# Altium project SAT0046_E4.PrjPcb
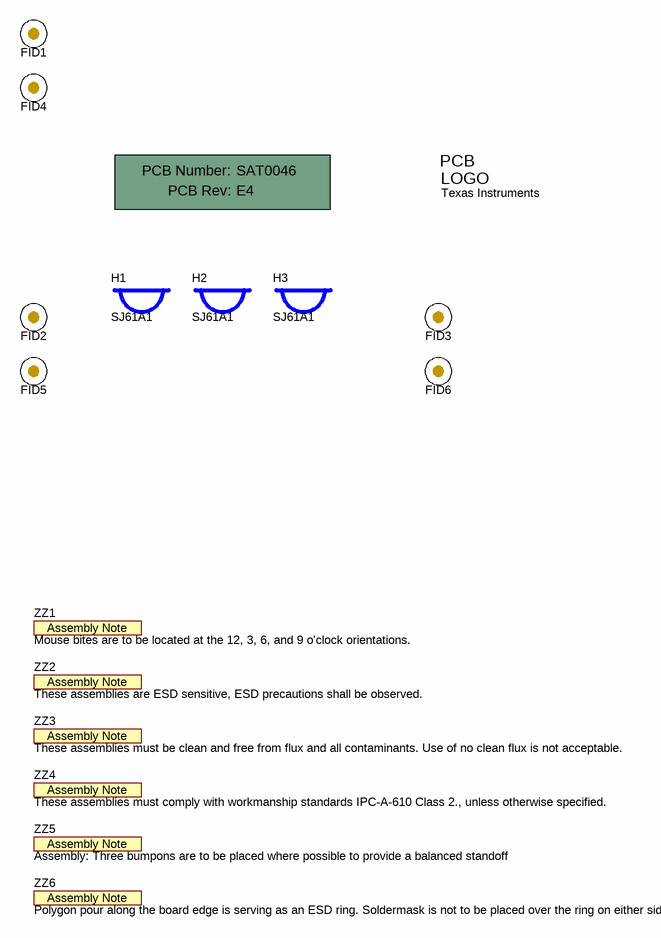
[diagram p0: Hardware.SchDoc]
TechSupport: http://www.ti.com/support; SCH_Rev: E4; PRJ_Title: SAT0046; PRJ_Number: SAT0046; PRJ_Engineer: Ajinder Singh; PRJ_Customer: Public Release; PCB_Rev: E4; PCB_Layout: Krypton Solutions LLC; CopyrightYear: 2012
3 sheets, 111 parts. Net scope: global (net labels, ports and power ports of the same name join across sheets).
Board file: SAT0046_E4.PcbDoc
Sheets:
  Hardware.SchDoc
  SAT0046_E4_Temp_Transmitter_System.SchDoc
  SAT0046_E4_MSP430.SchDoc

## Sheet Hardware.SchDoc: Hardware
size 431 x 279 mm; Date: Not shown in title block; ApprovedBy: Not shown in title block; CheckedBy: Not shown in title block; Author: Not shown in title block; CompanyName: Not shown in title block; DrawnBy: Ajinder Singh; Engineer: Not shown in title block; Organization: Not shown in title block; Address1: Not shown in title block; Address2: Not shown in title block; Address3: Not shown in title block; Address4: Not shown in title block; DocumentNumber: 1; Revision: Use project parameter SCH_Rev; SheetNumber: 1; SheetTotal: 1; PageSetup: Record=PageOptions|CenterHorizontal=True|CenterVertical=True|PrintScale=1.00|XCorrection=1.00|YCorrection=1.00|PrintKind=0|BorderSize=5000000|LeftOffset=0|BottomOffset=0|Orientation=2|PaperLength=1000|PaperWidth=1000|Scale=100|PaperSource=15|PrintQuality=600|MediaType=1|DitherType=10|PaperKind=Letter|PrintScaleMode=1

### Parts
!PCB1  Printed Circuit Board  (value not drawn)  (mechanical)
FID1  Fiducial  [Fiducial10-20]  (value not drawn)
FID2  Fiducial  [Fiducial10-20]  (value not drawn)
FID3  Fiducial  [Fiducial10-20]  (value not drawn)
FID4  Fiducial  [Fiducial10-20]  (value not drawn)
FID5  Fiducial  [Fiducial10-20]  (value not drawn)
FID6  Fiducial  [Fiducial10-20]  (value not drawn)
H1  SJ61A1  [Bumpon_SJ61A1]
H2  SJ61A1  [Bumpon_SJ61A1]
H3  SJ61A1  [Bumpon_SJ61A1]
Logo1  Texas Instruments  [TI_Symbol_Overlay_Small]  (no BOM)
ZZ1  Mouse bites are to be located at the 12, 3, 6, and 9 o'clock orientations.  [AssemblyNote]  (no BOM)
ZZ2  These assemblies are ESD sensitive, ESD precautions shall be observed.  [AssemblyNote]  (no BOM)
ZZ3  These assemblies must be clean and free from flux and all contaminants. Use of no clean flux is not acceptable.  [AssemblyNote]  (no BOM)
ZZ4  These assemblies must comply with workmanship standards IPC-A-610 Class 2., unless otherwise specified.  [AssemblyNote]  (no BOM)
ZZ5  Assembly: Three bumpons are to be placed where possible to provide a balanced standoff  [AssemblyNote]  (no BOM)
ZZ6  Polygon pour along the board edge is serving as an ESD ring. Soldermask is not to be placed over the ring on either side.  [AssemblyNote]  (no BOM)

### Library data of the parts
!PCB1 = PCB: Manufacturer: Any; PartNumber: SAT0046; SymbolCreator: a0412235
FID1-FID6 = Fiducial: Fiducial mark.  There is nothing to buy or mount.; SymbolCreator: codlsc
H1-H3 = SJ61A1: Bumpon, Cylindrical, 0.312 X 0.200, Black; Manufacturer: 3M; SymbolCreator: a0412235
Logo1 = TI_Logo: Texas Instrument Corporate Signature; SymbolCreator: codlsc
ZZ1-ZZ6 = AssemblyNote: SymbolCreator: codlsc

## Sheet SAT0046_E4_Temp_Transmitter_System.SchDoc: Temp_Transmitter_System
size 431 x 279 mm; Date: Not shown in title block; ApprovedBy: Not shown in title block; CheckedBy: Not shown in title block; Author: Not shown in title block; CompanyName: Not shown in title block; DrawnBy: Ajinder Singh; Engineer: Ajinder Singh; Organization: Not shown in title block; Address1: Not shown in title block; Address2: Not shown in title block; Address3: Not shown in title block; Address4: Not shown in title block; DocumentNumber: 1; Revision: E2; SheetNumber: 1; SheetTotal: 1; PageSetup: Record=PageOptions|CenterHorizontal=True|CenterVertical=True|PrintScale=1.00|XCorrection=1.00|YCorrection=1.00|PrintKind=0|BorderSize=5000000|LeftOffset=0|BottomOffset=0|Orientation=2|PaperLength=1000|PaperWidth=1000|Scale=100|PaperSource=15|PrintQuality=600|MediaType=1|DitherType=10|PaperKind=Letter|PrintScaleMode=1
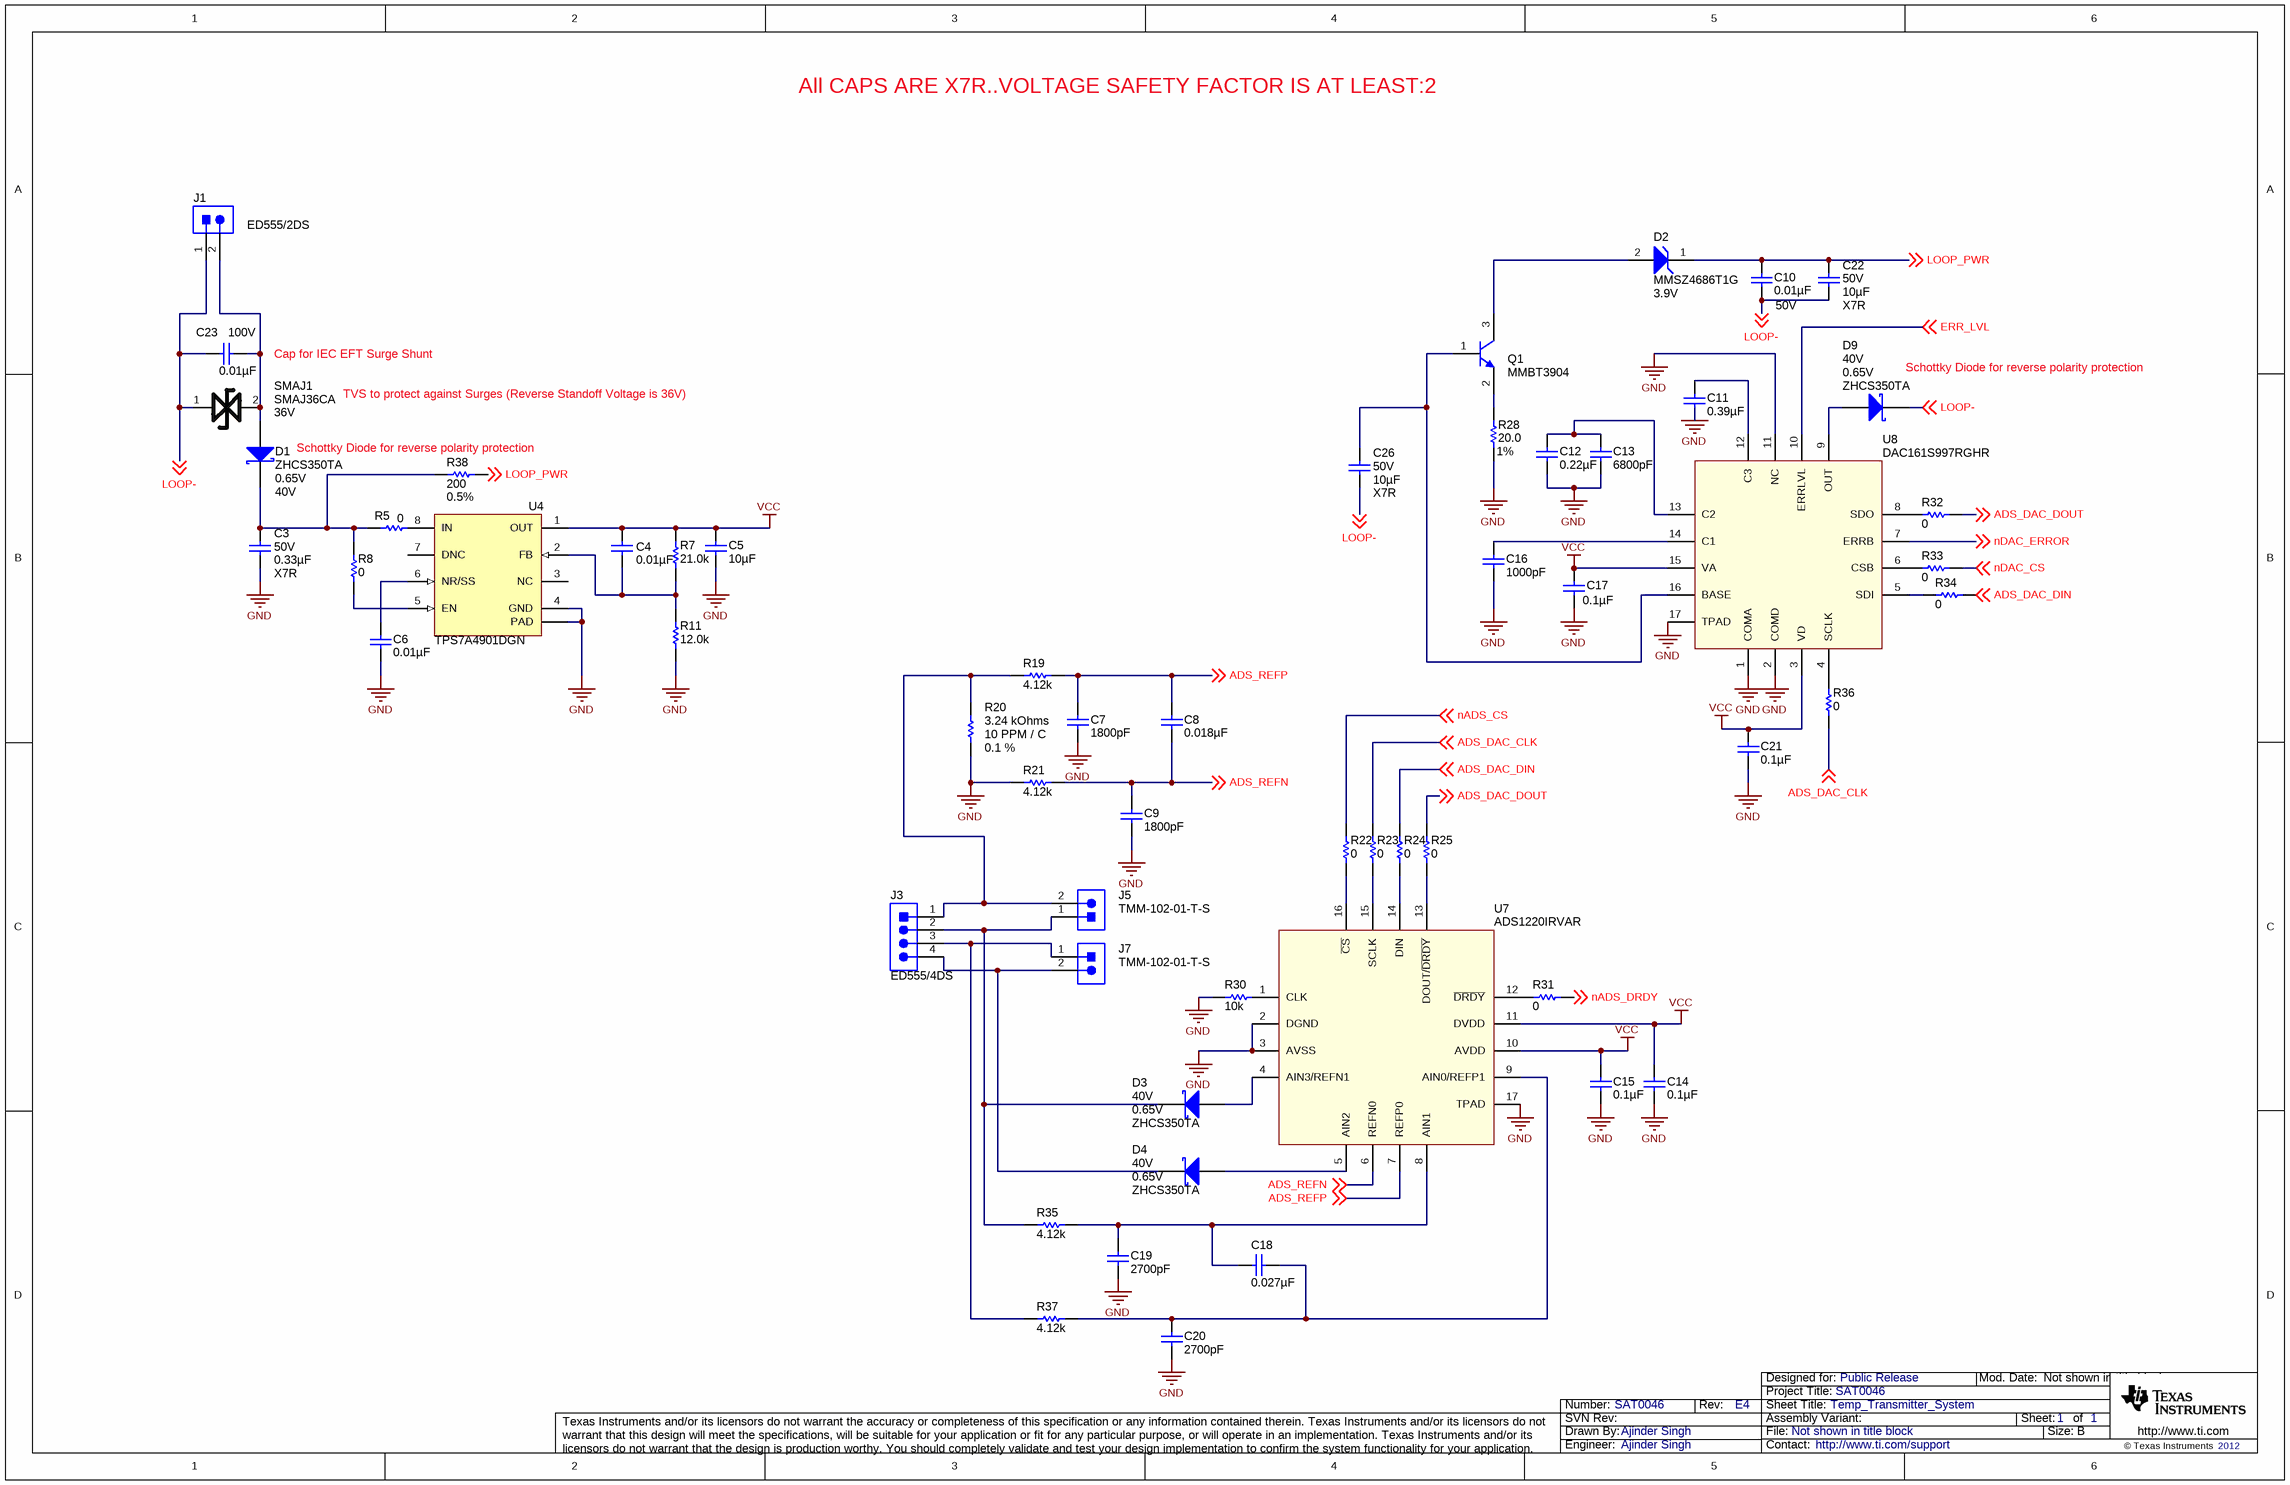
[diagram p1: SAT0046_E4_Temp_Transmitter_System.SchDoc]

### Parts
C3  ValueDisplayed: 0.33µF  Value2: 50V  TempCo: X7R  [1206]  (hidden comment: 12065C334KAT2A)
C4  ValueDisplayed: 0.01µF  [0603]  (hidden comment: C0603C103J5RACTU)
C5  ValueDisplayed: 10µF  [1206]  (hidden comment: GRM31CR71C106KAC7L)
C6  ValueDisplayed: 0.01µF  [0603]  (hidden comment: C0603C103J5RACTU)
C7  value 1800pF  [0603]  (hidden comment: Used in BOM report)
C8  ValueDisplayed: 0.018µF  [0603]  (hidden comment: C0603C183K1RACTU)
C9  value 1800pF  [0603]  (hidden comment: Used in BOM report)
C10  ValueDisplayed: 0.01µF  Value2: 50V  [0603]  (hidden comment: C0603C103J5RACTU)
C11  ValueDisplayed: 0.39µF  [1206]  (hidden comment: GRM31MR71H394KA01L)
C12  ValueDisplayed: 0.22µF  [1206]  (hidden comment: C1206C224J5RACTU)
C13  ValueDisplayed: 6800pF  [0603]  (hidden comment: C0603C682J5RACTU)
C14  ValueDisplayed: 0.1µF  [0603]  (hidden comment: C0603X104K4RACTU)
C15  ValueDisplayed: 0.1µF  [0603]  (hidden comment: C0603X104K4RACTU)
C16  ValueDisplayed: 1000pF  [0603]  (hidden comment: C0603C102J5RACTU)
C17  ValueDisplayed: 0.1µF  [0603]  (hidden comment: C0603X104K4RACTU)
C18  ValueDisplayed: 0.027µF  [0603]  (hidden comment: C0603C273K1RACTU)
C19  value 2700pF  [0603]  (hidden comment: Used in BOM report)
C20  value 2700pF  [0603]  (hidden comment: Used in BOM report)
C21  ValueDisplayed: 0.1µF  [0603]  (hidden comment: C0603X104K4RACTU)
C22  ValueDisplayed: 10µF  Value2: 50V  TempCo: X7R  [1210]  (hidden comment: GRM32ER71H106KA12L)
C23  ValueDisplayed: 0.01µF  Value2: 100V  [0603]  (hidden comment: C1608X7R2A103K)
C26  ValueDisplayed: 10µF  Value2: 50V  TempCo: X7R  [1210]  (hidden comment: GRM32ER71H106KA12L)
D1  ZHCS350TA  value 0.65V  Value2: 40V  [SOD-523]
D2  MMSZ4686T1G  value 3.9V  [SOD-123]
D3  ZHCS350TA  value 0.65V  Value2: 40V  [SOD-523]
D4  ZHCS350TA  value 0.65V  Value2: 40V  [SOD-523]
D9  ZHCS350TA  value 0.65V  Value2: 40V  [SOD-523]
J1  ED555/2DS  [TERM_BLK_ED555-2DS]
J3  ED555/4DS  [TERM_BLK_ED555-4DS]
J5  TMM-102-01-T-S  [CONN_TMM-102-01-T-S]
J7  TMM-102-01-T-S  [CONN_TMM-102-01-T-S]
Q1  MMBT3904  [SOT-23]
R5  value 0  [0402]  (hidden comment: CRCW04020000Z0ED)
R7  value 21.0k  [0603]  (hidden comment: RC0603FR-0721KL)
R8  value 0  [0402]  (hidden comment: CRCW04020000Z0ED)
R11  value 12.0k  [0603]  (hidden comment: RC0603FR-0712KL)
R19  value 4.12k  [1206]  (hidden comment: ERA-8AEB4121V)
R20  value 3.24 kOhms  TempCo: 10 PPM / C  Tolerance_%: 0.1 %  [1206]  (hidden comment: PFC-W1206R-12-3241-B)
R21  value 4.12k  [1206]  (hidden comment: ERA-8AEB4121V)
R22  value 0  [0402]  (hidden comment: CRCW04020000Z0ED)
R23  value 0  [0402]  (hidden comment: CRCW04020000Z0ED)
R24  value 0  [0402]  (hidden comment: CRCW04020000Z0ED)
R25  value 0  [0402]  (hidden comment: CRCW04020000Z0ED)
R28  value 20.0  Value1: 1%  [0603]  (hidden comment: CRCW060320R0FKEA)
R30  value 10k  [0402]  (hidden comment: CRCW040210K0FKEDHP)
R31  value 0  [0402]  (hidden comment: CRCW04020000Z0ED)
R32  value 0  [0402]  (hidden comment: CRCW04020000Z0ED)
R33  value 0  [0402]  (hidden comment: CRCW04020000Z0ED)
R34  value 0  [0402]  (hidden comment: CRCW04020000Z0ED)
R35  value 4.12k  [1206]  (hidden comment: ERA-8AEB4121V)
R36  value 0  [0402]  (hidden comment: CRCW04020000Z0ED)
R37  value 4.12k  [1206]  (hidden comment: ERA-8AEB4121V)
R38  value 200  Value1: 0.5%  [0603]  (hidden comment: RT0603DRE07200RL)
SMAJ1  Voltage - Reverse Standoff (Typ): 36V  [SMAJ36CA]  (hidden comment: SMAJ36CA)
U4  TPS7A4901DGN  [DGN0008D_N]
U7  ADS1220IRVAR  [ADS1220IRVAR]
U8  DAC161S997RGHR  [DAC161S997RGHR]

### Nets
GND: C3.2 C5.2 C6.2 C7.2 C9.2 C11.2 C12.2 C13.2 C14.2 C15.2 C16.2 C17.2 C19.2 C20.2 C21.2 R11.1 R20.1 R21.1 R28.1 R30.1 U4.4(GND) U4.9(PAD) U7.2(DGND) U7.3(AVSS) U7.17(TPAD) U8.1(COMA) U8.2(COMD) U8.11(NC) U8.17(TPAD)
VCC: C4.2 C5.1 C14.1 C15.1 C17.1 C21.1 R7.2 U4.1(OUT) U7.10(AVDD) U7.11(DVDD) U8.3(VD) U8.15(VA)
ADS_DAC_CLK: R23.2 R36.2 ; off-sheet ADS_DAC_CLK
ADS_DAC_DIN: R24.2 R34.1 ; off-sheet ADS_DAC_DIN
ADS_DAC_DOUT: R25.2 R32.1 ; off-sheet ADS_DAC_DOUT
ADS_REFN: C8.2 C9.1 R21.2 U7.6(REFN0) ; off-sheet ADS_REFN
ADS_REFP: C7.1 C8.1 R19.2 U7.7(REFP0) ; off-sheet ADS_REFP
ERR_LVL: U8.10(ERRLVL) ; off-sheet ERR_LVL
LOOP-: C10.2 C22.2 C23.2 C26.2 D9.1(K) J1.1 SMAJ1.1 ; off-sheet LOOP-
LOOP_PWR: C10.1 C22.1 D2.1(K) R38.2 ; off-sheet LOOP_PWR
nADS_CS: R22.2 ; off-sheet nADS_CS
nADS_DRDY: R31.1 ; off-sheet nADS_DRDY
nDAC_CS: R33.1 ; off-sheet nDAC_CS
nDAC_ERROR: U8.7(ERRB) ; off-sheet nDAC_ERROR
NetC3_1: C3.1 D1.1(K) R5.2 R8.1 R38.1
NetC4_1: C4.1 R7.1 R11.2 U4.2(FB)
NetC6_1: C6.1 U4.6(NR/SS)
NetC11_1: C11.1 U8.12(C3)
NetC12_1: C12.1 C13.1 U8.13(C2)
NetC16_1: C16.1 U8.14(C1)
NetC18_1: C18.1 C20.1 R37.2 U7.9(AIN0/REFP1)
NetC18_2: C18.2 C19.1 R35.2 U7.8(AIN1)
NetC23_1: C23.1 D1.2(A) J1.2 SMAJ1.2
NetC26_1: C26.1 Q1.1(B) U8.16(BASE)
NetD2_2: D2.2(A) Q1.3(C)
NetD3_1: D3.1(K) J3.2 J5.1 R35.1
NetD3_2: D3.2(A) U7.4(AIN3/REFN1)
NetD4_1: D4.1(K) J3.4 J7.2
NetD4_2: D4.2(A) U7.5(AIN2)
NetD9_2: D9.2(A) U8.9(OUT)
NetJ3_1: J3.1 J5.2 R19.1 R20.2
NetJ3_3: J3.3 J7.1 R37.1
NetQ1_2: Q1.2(E) R28.2
NetR5_1: R5.1 U4.8(IN)
NetR8_2: R8.2 U4.5(EN)
NetR22_1: R22.1 U7.16(~{CS})
NetR23_1: R23.1 U7.15(SCLK)
NetR24_1: R24.1 U7.14(DIN)
NetR25_1: R25.1 U7.13(DOUT/~{DRDY})
NetR30_2: R30.2 U7.1(CLK)
NetR31_2: R31.2 U7.12(~{DRDY})
NetR32_2: R32.2 U8.8(SDO)
NetR33_2: R33.2 U8.6(CSB)
NetR34_2: R34.2 U8.5(SDI)
NetR36_1: R36.1 U8.4(SCLK)

Not connected (* = marked no-connect by the designer): U4 3(NC) 7(DNC)

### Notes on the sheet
- All CAPS ARE X7R..VOLTAGE SAFETY FACTOR IS AT LEAST:2
- Cap for IEC EFT Surge Shunt
- (near D9) Schottky Diode for reverse
- polarity protection
- TVS to protect against Surges (Reverse Standoff Voltage is 36V)
- Schottky Diode for reverse
- (near R38) polarity protection

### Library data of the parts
C3 = 12065C334KAT2A: CAP, CERM, 0.33uF, 50V, +/-10%, X7R, 1206; Manufacturer: AVX; Polarized: N; CompType: Capacitor; U/M: EA; Cap_F: 0.00000033; Tolerance_%: 10; ESR_Ohm: 0.021; Value1: 0.021 ohm; VDC_V: 50; TaMin_C: -55; TaMax_C: 125
C4 C6 C10 = C0603C103J5RACTU: CAP, CERM, 0.01uF, 50V, +/-5%, X7R, 0603; Manufacturer: Kemet; Polarized: N; CompType: Capacitor; U/M: EA; Cap_F: 0.00000001; Tolerance_%: 5; Value1: Unknown; VDC_V: 50; TaMin_C: -55; TaMax_C: 125
C5 = GRM31CR71C106KAC7L: CAP, CERM, 10uF, 16V, +/-10%, X7R, 1206; Manufacturer: MuRata; Polarized: N; CompType: Capacitor; U/M: EA; Cap_F: 0.00001; Tolerance_%: 10; Value1: Unknown; VDC_V: 16; TaMin_C: -55; TaMax_C: 125
C7 C9 = C0603C182K1RACTU: CAP CER 1800PF 100V 10% X7R 0603; SymbolVersion: use current date i.e. 2008-05-20; SymbolCreator: Use a-id; CompType: Used in some BOM reports.  Useful for finding later.; U/M: EA, IN, or GM
C8 = C0603C183K1RACTU: CAP, CERM, 0.018uF, 100V, +/-10%, X7R, 0603; Manufacturer: Kemet; Polarized: N; CompType: Capacitor; U/M: EA; Cap_F: 0.000000018; Tolerance_%: 10; Value1: Unknown; VDC_V: 100; TaMin_C: -55; TaMax_C: 125
C11 = GRM31MR71H394KA01L: CAP, CERM, 0.39uF, 50V, +/-10%, X7R, 1206; Manufacturer: MuRata; Polarized: N; CompType: Capacitor; U/M: EA; Cap_F: 0.00000039; Tolerance_%: 10; Value1: Unknown; VDC_V: 50; TaMin_C: -55; TaMax_C: 125
C12 = C1206C224J5RACTU: CAP, CERM, 0.22uF, 50V, +/-5%, X7R, 1206; Manufacturer: Kemet; Polarized: N; CompType: Capacitor; U/M: EA; Cap_F: 0.00000022; Tolerance_%: 5; ESR_Ohm: 0.081; Value1: 0.081 ohm; VDC_V: 50; IRMS_A: 1.95; TaMin_C: -55; TaMax_C: 125
C13 = C0603C682J5RACTU: CAP, CERM, 6800pF, 50V, +/-5%, X7R, 0603; Manufacturer: Kemet; Polarized: N; CompType: Capacitor; U/M: EA; Cap_F: 0.0000000068; Tolerance_%: 5; Value1: Unknown; VDC_V: 50; TaMin_C: -55; TaMax_C: 125
C14 C15 C17 C21 = C0603X104K4RACTU: CAP, CERM, 0.1uF, 16V, +/-10%, X7R, 0603; Manufacturer: Kemet; Polarized: N; CompType: Capacitor; U/M: EA; Cap_F: 0.0000001; Tolerance_%: 10; Value1: Unknown; VDC_V: 16; TaMin_C: -55; TaMax_C: 125
C16 = C0603C102J5RACTU: CAP, CERM, 1000pF, 50V, +/-5%, X7R, 0603; Manufacturer: Kemet; Polarized: N; CompType: Capacitor; U/M: EA; Cap_F: 0.000000001; Tolerance_%: 5; Value1: Unknown; VDC_V: 50; TaMin_C: -55; TaMax_C: 125
C18 = C0603C273K1RACTU: CAP, CERM, 0.027uF, 100V, +/-10%, X7R, 0603; Manufacturer: Kemet; Polarized: N; CompType: Capacitor; U/M: EA; Cap_F: 0.000000027; Tolerance_%: 10; Value1: Unknown; VDC_V: 100; TaMin_C: -55; TaMax_C: 125
C19 C20 = C0603C272K1RACTU: CAP CER 2700PF 100V 10% X7R 0603; SymbolVersion: use current date i.e. 2008-05-20; SymbolCreator: Use a-id; CompType: Used in some BOM reports.  Useful for finding later.; U/M: EA, IN, or GM
C22 C26 = GRM32ER71H106KA12L: CAP, CERM, 10uF, 50V, +/-10%, X7R, 1210; Manufacturer: MuRata; Polarized: N; CompType: Capacitor; U/M: EA; Cap_F: 0.00001; Tolerance_%: 10; Value1: Unknown; VDC_V: 50; TaMin_C: -55; TaMax_C: 125
C23 = C1608X7R2A103K: CAP, CERM, 0.01uF, 100V, +/-10%, X7R, 0603; Manufacturer: TDK; Polarized: N; CompType: Capacitor; U/M: EA; Cap_F: 0.00000001; Tolerance_%: 10; ESR_Ohm: 0.0661; Value1: 0.0661 ohm; VDC_V: 100; TaMin_C: -55; TaMax_C: 125
D1 D3 D4 D9 = ZHCS350TA: Diode, Schottky, 40V, 0.35A, SOD-523; Manufacturer: Diodes Inc.; U/M: EA; Vf_V: 0.65; Io_A: 0.35; Vr_V: 40
D2 = MMSZ4686T1G: Diode, Zener, 3.9V, 500mW, SOD-123; Manufacturer: ON Semiconductor; U/M: EA; Power_W: 0.5; Vz_V: 3.9; Value1: 0.5W; RJA_CperW: 340
J1 = ED555/2DS: Terminal Block, 6A, 3.5mm Pitch, 2-Pos, TH; Manufacturer: On-Shore Technology; SymbolCreator: a0412235; CompType: Connector; U/M: EA
J3 = ED555/4DS: Terminal Block, 6A, 3.5mm Pitch, 4-Pos, TH; Manufacturer: On-Shore Technology; SymbolCreator: a0412235; CompType: Connector; U/M: EA
J5 J7 = TMM-102-01-T-S: Header, 2mm, 2x1, Tin, TH; Manufacturer: Samtec; SymbolCreator: a0412235; CompType: Connector; U/M: EA
Q1 = MMBT3904, Fairchild Semiconductor: Transistor, NPN, 40V, 0.2A, SOT-23; CompType: BJT; PNP: 0; NPN: 1; Vceo_V: 40; Vcesat1_V: 0.2; Value: 0.2V; HfeMax: 300; TaMin_C: -55; TaMax_C: 150; U/M: EA
R5 R8 R22-R25 R31-R34 R36 = CRCW04020000Z0ED: RES, 0 ohm, 5%, 0.063W, 0402; Manufacturer: Vishay-Dale; CompType: Resistor; Value_Code: 0000; Tolerance_%: 5; Power_W: 0.063; VDC_V: 50; TempCo: 200 ppm/C; EIA_Code: E24; U/M: EA
R7 = RC0603FR-0721KL: RES, 21.0k ohm, 1%, 0.1W, 0603; Manufacturer: Yageo America; CompType: Resistor; Res_ohm: 21000; Value_Code: 21k0; Tolerance_%: 1; Power_W: 0.1; VDC_V: 150; TempCo: 200 ppm/C; EIA_Code: E96; U/M: EA
R11 = RC0603FR-0712KL: RES, 12.0k ohm, 1%, 0.1W, 0603; Manufacturer: Yageo America; CompType: Resistor; Res_ohm: 12000; Value_Code: 12k0; Tolerance_%: 1; Power_W: 0.1; VDC_V: 150; TempCo: 200 ppm/C; U/M: EA
R19 R21 R35 R37 = ERA-8AEB4121V: RES 4.12K OHM 1/4W .1% 1206 SMD; Manufacturer: Panasonic Electronic Components; Tolerance_%: ±0.1%; Power_W: 0.25W, 1/4W; TempCo: ±25ppm/°C
R20 = 66-PFC 12L3.24k-B: Thin Film Resistors - SMD 3.24K .1% 10ppm; Manufacturer: IRC / TT electronics; Power_W: 330 mW; Case Height: 0.6 mm; Case Length: 3.2 mm; Case Width: 1.6 mm
R28 = CRCW060320R0FKEA: RES, 20.0 ohm, 1%, 0.1W, 0603; Manufacturer: Vishay-Dale; CompType: Resistor; Res_ohm: 20; Value_Code: 20R0; Tolerance_%: 1; Power_W: 0.1; VDC_V: 75; TempCo: 100 ppm/C; EIA_Code: E96; U/M: EA
R30 = Resistor: RES, xxx ohm, x%, xW, [PackageReference]; Manufacturer: Vishay Dale; U/M: EA; Description: RES 10.0K OHM .125W 1% 0402 SMD; Tolerance_%: ±1%; Power_W: 0.125W, 1/8W; TempCo: ±100ppm/°C
R38 = RT0603DRE07200RL: RES, 200 ohm, 0.5%, 0.1W, 0603; Manufacturer: Yageo America; CompType: Resistor; Value_Code: 200R; Tolerance_%: 0.5; Power_W: 0.1; VDC_V: 75; TempCo: 50 ppm/C; EIA_Code: E192; U/M: EA
SMAJ1 = SMAJ36CA: DIODE TVS 36V 400W BI 5% SMD; Manufacturer: Bourns Inc.; Voltage - Breakdown: 40V; Polarization: Bidirectional
U4 = TPS7A4901DGN: +36V, +150mA, Ultralow-Noise, Positive LINEAR REGULATOR, DGN0008D; Alternate Manufacturer: None; Manufacturer: Texas Instruments; SymbolCreator: a0411947; CompType: IC; U/M: EA
U7 = ADS1220IRVAR: Low-Power, Low-Noise, 24-Bit, Analog-to-Digital Converter for Small-Signal Sensors; Manufacturer: Texas Instrumetns
U8 = DAC161S997RGHR: IC DAC 16BIT SPI/SRL 16WQFN; Manufacturer: Texas Instruments; Resolution (Bits): 16 b; Data Interface: DSP, MICROWIRE™, QSPI™, Serial, SPI™; Voltage Supply Source: Analog and Digital; Voltage - Supply: 2.7 V ~ 3.6 V

## Sheet SAT0046_E4_MSP430.SchDoc: MSP430
size 431 x 279 mm; Date: Not shown in title block; ApprovedBy: Not shown in title block; CheckedBy: Not shown in title block; Author: Not shown in title block; CompanyName: Not shown in title block; DrawnBy: Ajinder Singh; Engineer: Not shown in title block; Organization: Not shown in title block; Address1: Not shown in title block; Address2: Not shown in title block; Address3: Not shown in title block; Address4: Not shown in title block; DocumentNumber: 1; Revision: Use project parameter SCH_Rev; SheetNumber: 1; SheetTotal: 1; PageSetup: Record=PageOptions|CenterHorizontal=True|CenterVertical=True|PrintScale=1.00|XCorrection=1.00|YCorrection=1.00|PrintKind=0|BorderSize=5000000|LeftOffset=0|BottomOffset=0|Orientation=2|PaperLength=1000|PaperWidth=1000|Scale=100|PaperSource=15|PrintQuality=600|MediaType=1|DitherType=10|PaperKind=Letter|PrintScaleMode=1
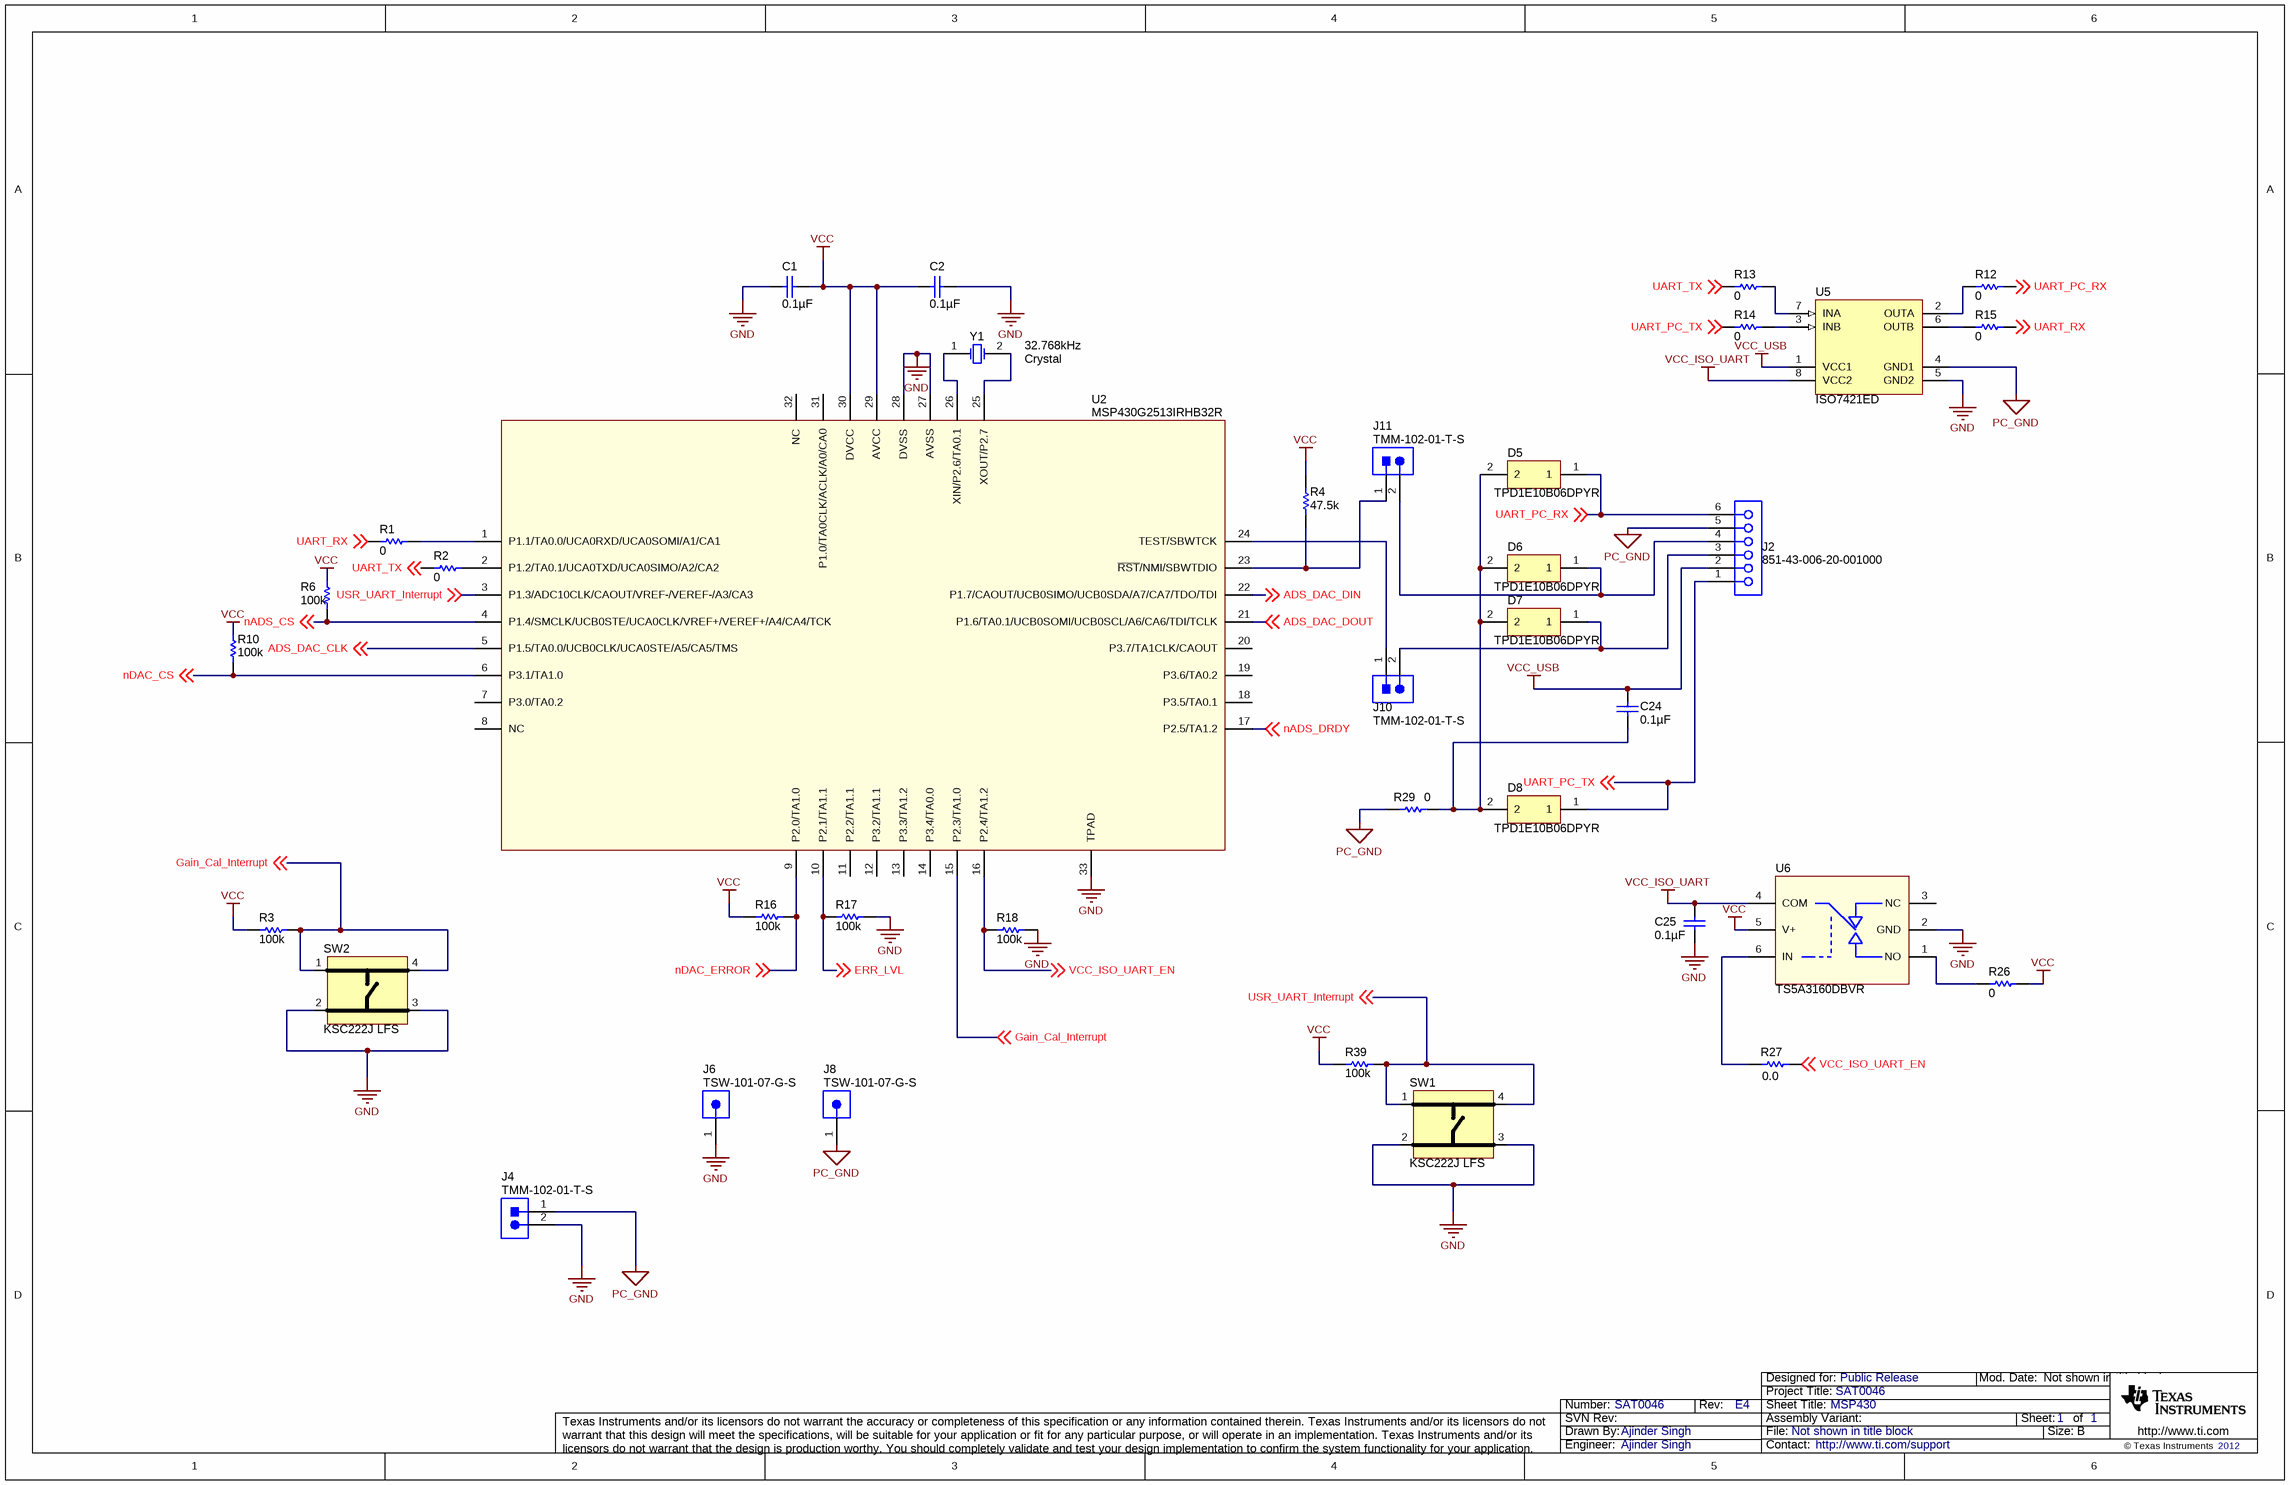
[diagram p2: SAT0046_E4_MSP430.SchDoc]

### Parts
C1  ValueDisplayed: 0.1µF  [0603]  (hidden comment: C0603X104K4RACTU)
C2  ValueDisplayed: 0.1µF  [0603]  (hidden comment: C0603X104K4RACTU)
C24  ValueDisplayed: 0.1µF  [0603]  (hidden comment: C0603X104K4RACTU)
C25  ValueDisplayed: 0.1µF  [0603]  (hidden comment: C0603X104K4RACTU)
D5  TPD1E10B06DPYR  [DPY0002A_N]
D6  TPD1E10B06DPYR  [DPY0002A_N]
D7  TPD1E10B06DPYR  [DPY0002A_N]
D8  TPD1E10B06DPYR  [DPY0002A_N]
J2  851-43-006-20-001000  [CONN_851-43-006-20-001000]
J4  TMM-102-01-T-S  [CONN_TMM-102-01-T-S]
J6  TSW-101-07-G-S  [TSW-101-07-G-S]
J8  TSW-101-07-G-S  [TSW-101-07-G-S]
J10  TMM-102-01-T-S  [CONN_TMM-102-01-T-S]
J11  TMM-102-01-T-S  [CONN_TMM-102-01-T-S]
R1  value 0  [0402]  (hidden comment: CRCW04020000Z0ED)
R2  value 0  [0402]  (hidden comment: CRCW04020000Z0ED)
R3  value 100k  [0603]  (hidden comment: RT0603BRD07100KL)
R4  value 47.5k  [0603]  (hidden comment: RG1608P-4752-B-T5)
R6  value 100k  [0603]  (hidden comment: RT0603BRD07100KL)
R10  value 100k  [0603]  (hidden comment: RT0603BRD07100KL)
R12  value 0  [0402]  (hidden comment: CRCW04020000Z0ED)
R13  value 0  [0402]  (hidden comment: CRCW04020000Z0ED)
R14  value 0  [0402]  (hidden comment: CRCW04020000Z0ED)
R15  value 0  [0402]  (hidden comment: CRCW04020000Z0ED)
R16  value 100k  [0603]  (hidden comment: RT0603BRD07100KL)
R17  value 100k  [0603]  (hidden comment: RT0603BRD07100KL)
R18  value 100k  [0603]  (hidden comment: RT0603BRD07100KL)
R26  value 0  [0402]  (hidden comment: CRCW04020000Z0ED)
R27  value 0.0  [0603]  (hidden comment: ERJ-3GEY0R00V)
R29  value 0  [0402]  (hidden comment: CRCW04020000Z0ED)
R39  value 100k  [0603]  (hidden comment: RT0603BRD07100KL)
SW1  KSC222J LFS  [KSC222J LFS]
SW2  KSC222J LFS  [KSC222J LFS]
U2  MSP430G2513IRHB32R  [MSP430G2513IRHB32T]
U5  ISO7421ED  [ISO7421ED]
U6  TS5A3160DBVR  [TS5A3160DBV]
Y1  Frequency: 32.768kHz  CompType: Crystal  [XTAL_NX3215SA]  (hidden comment: NX3215SA-32.768K-STD-MUS-2)

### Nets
GND: C1.2 C2.1 C25.2 J4.2 J6.1 R17.1 R18.1 SW1.2 SW1.3 SW2.2 SW2.3 U2.27(AVSS) U2.28(DVSS) U2.33(TPAD) U5.5(GND2) U6.2(GND)
PC_GND: J2.5 J4.1 J8.1 R29.2 U5.4(GND1)
VCC: C1.1 C2.2 R3.2 R4.2 R6.2 R10.2 R16.2 R26.2 R39.2 U2.29(AVCC) U2.30(DVCC) U6.5(V+)
VCC_ISO_UART: C25.1 U5.8(VCC2) U6.4(COM)
VCC_USB: C24.1 J2.2 U5.1(VCC1)
ADS_DAC_CLK: U2.5(P1.5/TA0.0/UCB0CLK/UCA0STE/A5/CA5/TMS) ; off-sheet ADS_DAC_CLK
ADS_DAC_DIN: U2.22(P1.7/CAOUT/UCB0SIMO/UCB0SDA/A7/CA7/TDO/TDI) ; off-sheet ADS_DAC_DIN
ADS_DAC_DOUT: U2.21(P1.6/TA0.1/UCB0SOMI/UCB0SCL/A6/CA6/TDI/TCLK) ; off-sheet ADS_DAC_DOUT
ERR_LVL: R17.2 U2.10(P2.1/TA1.1) ; off-sheet ERR_LVL
Gain_Cal_Interrupt: R3.1 SW2.1 SW2.4 U2.15(P2.3/TA1.0) ; off-sheet Gain_Cal_Interrupt
nADS_CS: R6.1 U2.4(P1.4/SMCLK/UCB0STE/UCA0CLK/VREF+/VEREF+/A4/CA4/TCK) ; off-sheet nADS_CS
nADS_DRDY: U2.17(P2.5/TA1.2) ; off-sheet nADS_DRDY
nDAC_CS: R10.1 U2.6(P3.1/TA1.0) ; off-sheet nDAC_CS
nDAC_ERROR: R16.1 U2.9(P2.0/TA1.0) ; off-sheet nDAC_ERROR
UART_PC_RX: D5.1 J2.6 R12.1 ; off-sheet UART_PC_RX
UART_PC_TX: D8.1 J2.1 R14.1 ; off-sheet UART_PC_TX
UART_RX: R1.2 R15.2 ; off-sheet UART_RX
UART_TX: R2.2 R13.2 ; off-sheet UART_TX
USR_UART_Interrupt: R39.1 SW1.1 SW1.4 U2.3(P1.3/ADC10CLK/CAOUT/VREF-/VEREF-/A3/CA3) ; off-sheet USR_UART_Interrupt
VCC_ISO_UART_EN: R18.2 R27.2 U2.16(P2.4/TA1.2) ; off-sheet VCC_ISO_UART_EN
NetC24_2: C24.2 D5.2 D6.2 D7.2 D8.2 R29.1
NetD6_1: D6.1 J2.4 J11.2
NetD7_1: D7.1 J2.3 J10.2
NetJ10_1: J10.1 U2.24(TEST/SBWTCK)
NetJ11_1: J11.1 R4.1 U2.23(~{RST}/NMI/SBWTDIO)
NetR1_1: R1.1 U2.1(P1.1/TA0.0/UCA0RXD/UCA0SOMI/A1/CA1)
NetR2_1: R2.1 U2.2(P1.2/TA0.1/UCA0TXD/UCA0SIMO/A2/CA2)
NetR12_2: R12.2 U5.2(OUTA)
NetR13_1: R13.1 U5.7(INA)
NetR14_2: R14.2 U5.3(INB)
NetR15_1: R15.1 U5.6(OUTB)
NetR26_1: R26.1 U6.1(NO)
NetR27_1: R27.1 U6.6(IN)
NetU2_25: U2.25(XOUT/P2.7) Y1.2(OSC2)
NetU2_26: U2.26(XIN/P2.6/TA0.1) Y1.1(OSC1)

Not connected (* = marked no-connect by the designer): U2 7(P3.0/TA0.2) 8(NC) 11(P2.2/TA1.1) 12(P3.2/TA1.1) 13(P3.3/TA1.2) 14(P3.4/TA0.0) 18(P3.5/TA0.1) 19(P3.6/TA0.2) 20(P3.7/TA1CLK/CAOUT) 31(P1.0/TA0CLK/ACLK/A0/CA0) 32(NC); U6 3(NC)

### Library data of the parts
C1 C2 C24 C25 = C0603X104K4RACTU: as C14 on sheet SAT0046_E4_Temp_Transmitter_System
D5-D8 = TPD1E10B06DPYR: ESD in 0402 Package with 10 pF Capacitance and 6 V Breakdown, 1 Channel, -40 to +125 degC, 2-pin X2SON (DPY), Green (RoHS & no Sb/Br); Manufacturer: Texas Instruments; Alternate Manufacturer: None; Alternate PartNumber: Equivalent; Breakdown Voltage(Min)(V): 6; Eco-Plan: TBD; IEC 61000-4-2 Air-Gap(+/- kV): 30; IO Capacitance(Typ)(pF): 10; SubFamily: ESD Solution
J2 = 851-43-006-20-001000: Receptacle, 50mil, 6x1, R/A, TH; Manufacturer: Mill-Max; SymbolCreator: a0411947; U/M: EA
J4 J10 J11 = TMM-102-01-T-S: as J5 on sheet SAT0046_E4_Temp_Transmitter_System
J6 J8 = TSW-101-07-G-S: Header, TH, 100mil, 1pos, Gold plated, 230 mil above insulator; Manufacturer: Samtec; SymbolCreator: a0412235; U/M: EA
R1 R2 R12-R15 R26 R29 = CRCW04020000Z0ED: as R5 on sheet SAT0046_E4_Temp_Transmitter_System
R3 R6 R10 R16-R18 R39 = RT0603BRD07100KL: RES, 100k ohm, 0.1%, 0.1W, 0603; Manufacturer: Yageo America; CompType: Resistor; Res_ohm: 100000; Tolerance_%: 0.1; VDC_V: 75; TempCo: 25 ppm/C; EIA_Code: E192; U/M: EA
R4 = RG1608P-4752-B-T5: RES, 47.5k ohm, 0.1%, 0.1W, 0603; Manufacturer: Susumu Co Ltd; CompType: Resistor; Res_ohm: 47500; Value_Code: 47k5; Tolerance_%: 0.1; VDC_V: 75; TempCo: 25 ppm/C; EIA_Code: E192; U/M: EA
R27 = Resistor: RES 0.0 OHM 1/10W JUMP 0603 SMD; Manufacturer: Panasonic Electronic Components; Power_W: 0.1W, 1/10W; Tolerance_%: Jumper
SW1 SW2 = KSC222J LFS: SWITCH TACTILE SPST-NO 0.05A 32V; Manufacturer: C&K Components; Switch Function: Off-Mom; Actuator Orientation: Top Actuated; Ingress Protection: IP67 - Dust Tight, Waterproof; Operating Force: 160gf; Outline: 6.20mm x 6.20mm; Illumination: Non-Illuminated; Contact Rating @ Voltage: 0.05A @ 32VDC; Actuator Height off PCB, from Pins: 3.50mm; Actuator Type: Standard; Mechanical Life: 1,000,000 Cycles; Switch Travel: 0.35mm
U2 = MSP430G2513RHB32T: IC MCU 16BIT 16KB FLASH 32QFN; Manufacturer: Texas Instruments; Core Size: 16-Bit; Speed: 16MHz; Connectivity: I²C, IrDA, LIN, SCI, SPI, UART/USART; Peripherals: Brown-out Detect/Reset, DMA, POR, PWM, WDT; Number of I /O: 24; Program Memory Size: 16KB (16K x 8); RAM Size: 512 x 8; Voltage - Supply (Vcc/Vdd): 1.8 V ~ 3.6 V; Oscillator Type: Internal
U5 = ISO7421ED: 50 Mbps Low-Power Dual Channels Digital Isolator, 3.3 V / 5 V, -40 to +125 degC, 8-pin SOIC (D), Green (RoHS & no Sb/Br); Manufacturer: Texas Instruments; Alternate Manufacturer: None; Alternate PartNumber: Equivalent; Datarate(Mbps): 50; Eco-Plan: TBD; Insulation Rating(VRMS): 2500; Prop Delay(Max)(ns): 11; Rating: Catalog; Supply Voltage(s)(V): 3.3, 5; TTL/CMOS Input Threshold: TTL
U6 = TS5A3160DBVR: IC SWITCH SPDT SOT23-6; Manufacturer: Texas Instruments; Circuit: 1 x SPDT; Voltage - Supply, Single/Dual (±): 1.65 V ~ 5.5 V; Voltage Supply Source: Single Supply; Current - Supply: 10nA; On-State Resistance: 900 mOhm
Y1 = NX3215SA-32.768K-STD-MUS-2: Crystal, 32.768kHz, 12.5pF, SMD; Manufacturer: NDK; SymbolCreator: a0412235; U/M: EA; TaMin_C: -40; TaMax_C: 125; Frequency Stability: ±20ppm

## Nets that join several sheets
GND: SAT0046_E4_Temp_Transmitter_System (29 pins), SAT0046_E4_MSP430 (16 pins)
VCC: SAT0046_E4_Temp_Transmitter_System (12 pins), SAT0046_E4_MSP430 (12 pins)
ADS_DAC_CLK: SAT0046_E4_Temp_Transmitter_System (R23.2 R36.2), SAT0046_E4_MSP430 (U2.5)
ADS_DAC_DIN: SAT0046_E4_Temp_Transmitter_System (R24.2 R34.1), SAT0046_E4_MSP430 (U2.22)
ADS_DAC_DOUT: SAT0046_E4_Temp_Transmitter_System (R25.2 R32.1), SAT0046_E4_MSP430 (U2.21)
ERR_LVL: SAT0046_E4_Temp_Transmitter_System (U8.10), SAT0046_E4_MSP430 (R17.2 U2.10)
nADS_CS: SAT0046_E4_Temp_Transmitter_System (R22.2), SAT0046_E4_MSP430 (R6.1 U2.4)
nADS_DRDY: SAT0046_E4_Temp_Transmitter_System (R31.1), SAT0046_E4_MSP430 (U2.17)
nDAC_CS: SAT0046_E4_Temp_Transmitter_System (R33.1), SAT0046_E4_MSP430 (R10.1 U2.6)
nDAC_ERROR: SAT0046_E4_Temp_Transmitter_System (U8.7), SAT0046_E4_MSP430 (R16.1 U2.9)

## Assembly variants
001: all parts fitted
